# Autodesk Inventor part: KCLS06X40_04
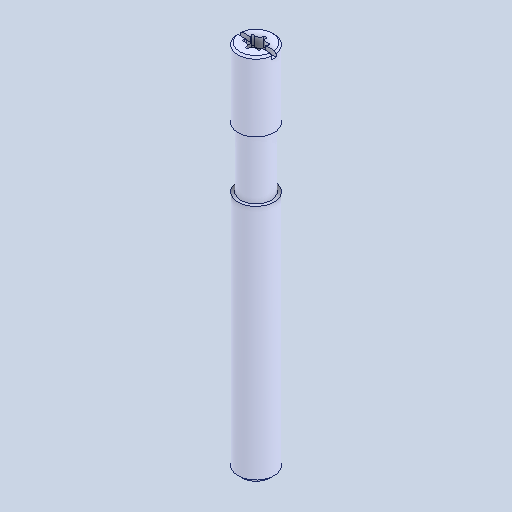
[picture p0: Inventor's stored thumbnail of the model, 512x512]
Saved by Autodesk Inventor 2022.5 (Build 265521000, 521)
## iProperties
Created: 2024-08
Part Number: KCLS06X40_04
Material: 一般
Document SubType Name: Modeling
Designer: ImaoCorp
Density: 1 g/cm^3
Appearance: 既定
Author: ImaoCorp
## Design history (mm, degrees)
feature "KCLS06X40_04"
node "ソリッド1"
